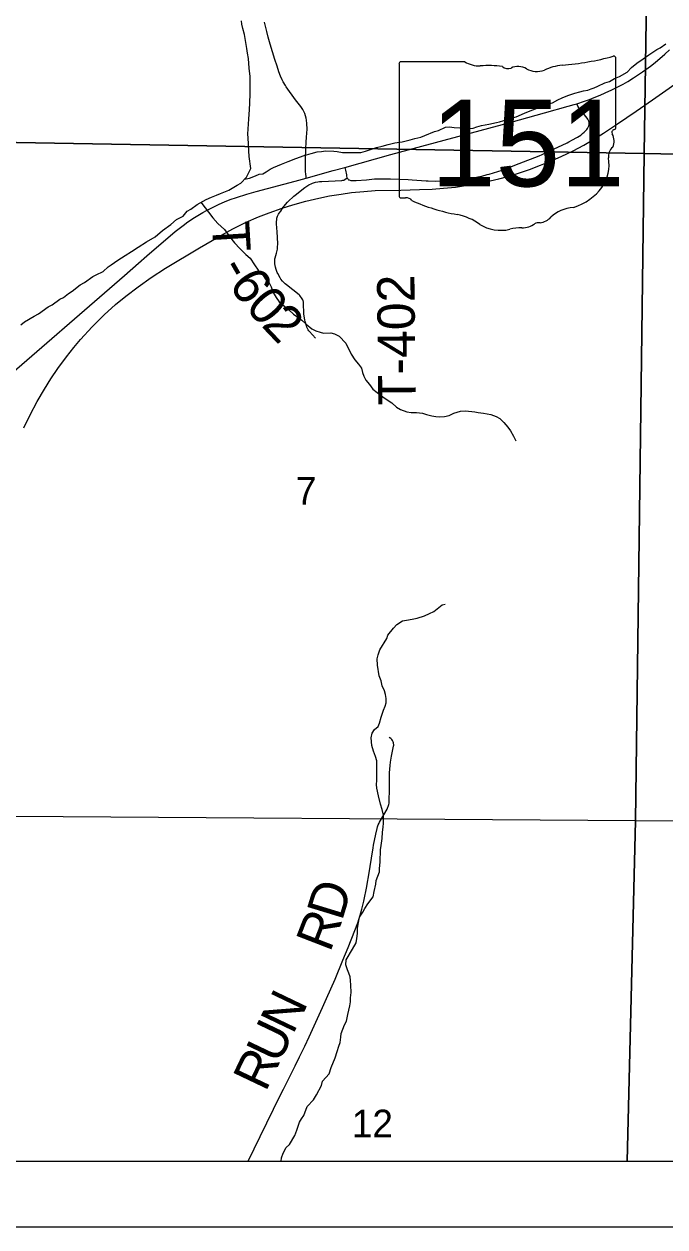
# Model space of a CAD drawing. Extents: x -1.2 to 34, y -8.5 to 22.
# Drawn here: x 3.48 to 4.454, y 14 to 15.827 of the extents above; entities that cross this region are included whole.
import ezdxf

# ---------------------------------------------------------------- set-up
doc = ezdxf.new("R2010")
doc.units = 0
for name, color, linetype in [('GM_X_Minor_River', 7, 'Continuous'), ('GM_X_Rail_Line', 7, 'Continuous'), ('GM_X_Section', 7, 'Continuous'), ('GM_X_Section_Text', 7, 'Continuous'), ('GM_X_State_Location', 7, 'Continuous'), ('GM_X_State_Route', 7, 'Continuous'), ('GM_X_State_Shield', 7, 'Continuous'), ('GM_X_Township_Road', 7, 'Continuous'), ('GM_X_Township_Road_Text', 7, 'Continuous'), ('GM_X_Unincorporated_Text', 7, 'Continuous'), ('SH_Cut_Line', 7, 'Continuous'), ('SH_Data', 7, 'Continuous')]:
    doc.layers.add(name, color=color, linetype=linetype)

msp = doc.modelspace()

# ---------------------------------------------------------------- linework, layer by layer
at = {"layer": 'GM_X_Minor_River'}
for points in [[(3.4755, 15.3701), (3.4808, 15.3747), (3.4954, 15.3833), (3.5022, 15.3869), (3.5168, 15.3977), (3.5232, 15.4009), (3.5344, 15.4094), (3.54, 15.4118), (3.5479, 15.418), (3.5535, 15.4215), (3.5655, 15.4312), (3.5719, 15.4347), (3.5846, 15.4437), (3.5899, 15.4464), (3.6004, 15.4512), (3.6079, 15.4585), (3.6128, 15.4616), (3.6225, 15.4686), (3.6341, 15.4757), (3.6435, 15.4815), (3.6536, 15.4885), (3.6664, 15.4963), (3.6795, 15.5038), (3.6908, 15.5135), (3.7031, 15.5228), (3.7117, 15.5305), (3.7219, 15.5353), (3.7282, 15.543), (3.7338, 15.5461), (3.7432, 15.5531), (3.7567, 15.5609), (3.765, 15.5641), (3.7725, 15.5672), (3.7785, 15.57), (3.7913, 15.5748), (3.7988, 15.5794), (3.8041, 15.5826), (3.8097, 15.5853), (3.8179, 15.5946), (3.8246, 15.608), (3.8224, 15.6262), (3.8219, 15.6346), (3.8205, 15.6544), (3.8204, 15.6597), (3.8206, 15.6681), (3.8213, 15.6749), (3.8216, 15.6833), (3.8225, 15.697), (3.8231, 15.7077), (3.8237, 15.7214), (3.8238, 15.7355), (3.8237, 15.7473), (3.8223, 15.7602), (3.821, 15.7747), (3.8197, 15.783), (3.8185, 15.7899), (3.8152, 15.8111), (3.8127, 15.8206), (3.8111, 15.827), (3.8103, 15.832)], [(3.8151, 15.5914), (3.8229, 15.5931), (3.8319, 15.5967), (3.8372, 15.5991), (3.8432, 15.5999), (3.8481, 15.6027), (3.8541, 15.6066), (3.8594, 15.6093), (3.8714, 15.6141), (3.8816, 15.6184), (3.8932, 15.6231), (3.9057, 15.6275), (3.9166, 15.6307), (3.9253, 15.6332), (3.9321, 15.6336), (3.9381, 15.6345), (3.9506, 15.6339), (3.9556, 15.6336), (3.9639, 15.6322), (3.9757, 15.632), (3.9916, 15.6323), (3.9987, 15.6339), (4.0051, 15.6359), (4.0157, 15.6399), (4.024, 15.6415), (4.0334, 15.6443), (4.0436, 15.6468), (4.0546, 15.6481), (4.0666, 15.6513), (4.0738, 15.6533), (4.0828, 15.6554), (4.0889, 15.6581), (4.1035, 15.6641), (4.1096, 15.6657), (4.1205, 15.6704), (4.1265, 15.6709), (4.1334, 15.6702), (4.1421, 15.6696), (4.1493, 15.669), (4.1569, 15.6687), (4.1622, 15.6691), (4.1678, 15.6711), (4.175, 15.6732), (4.1863, 15.6752), (4.1976, 15.6777), (4.2025, 15.6785), (4.2089, 15.6805), (4.2221, 15.6849), (4.2278, 15.6861), (4.2402, 15.6917), (4.2466, 15.6944), (4.2594, 15.6996), (4.2714, 15.7047), (4.2831, 15.7075), (4.291, 15.7122), (4.2974, 15.715), (4.3061, 15.7189), (4.317, 15.7222), (4.3242, 15.7242), (4.3302, 15.7258), (4.3366, 15.727), (4.3415, 15.729), (4.3464, 15.7302), (4.3517, 15.733), (4.3626, 15.7377), (4.3694, 15.7401), (4.3773, 15.7444), (4.3844, 15.7476), (4.3964, 15.7542), (4.4028, 15.7612), (4.411, 15.7678), (4.4204, 15.7744), (4.4294, 15.7806), (4.4414, 15.7884), (4.4462, 15.7911), (4.4552, 15.797)], [(3.7489, 15.5564), (3.767, 15.5329), (3.7747, 15.5243), (3.7846, 15.5149), (3.7924, 15.5044), (3.7997, 15.495), (3.8082, 15.486), (3.817, 15.477), (3.8235, 15.4717), (3.8301, 15.4616), (3.8359, 15.4533), (3.8424, 15.4465), (3.8471, 15.4397), (3.8525, 15.4341), (3.8556, 15.4281), (3.8587, 15.4194), (3.8634, 15.4118), (3.8676, 15.4054), (3.8765, 15.3979), (3.8822, 15.3931), (3.8895, 15.3867), (3.896, 15.3819), (3.9021, 15.3774), (3.909, 15.3714), (3.9175, 15.3643), (3.9236, 15.3614), (3.93, 15.3592), (3.935, 15.3577), (3.946, 15.3579), (3.952, 15.3565), (3.9589, 15.3532), (3.9689, 15.3426), (3.9771, 15.3256), (3.9829, 15.317), (3.9883, 15.3106), (3.9929, 15.3046), (3.9945, 15.2981), (3.9965, 15.2921), (3.9996, 15.286), (4.0047, 15.2796), (4.0101, 15.2725), (4.0166, 15.2673), (4.0273, 15.2594), (4.0388, 15.252), (4.046, 15.2453), (4.0518, 15.2415), (4.0617, 15.2383), (4.0681, 15.2372), (4.0761, 15.237), (4.0856, 15.2363), (4.0916, 15.2342), (4.0996, 15.232), (4.1057, 15.2309), (4.1106, 15.2303), (4.119, 15.2308), (4.1257, 15.2328), (4.1329, 15.2359), (4.1431, 15.2391), (4.1506, 15.2396), (4.1647, 15.2383), (4.17, 15.2373), (4.1783, 15.2359), (4.189, 15.2341), (4.1973, 15.2312), (4.2031, 15.2279), (4.2088, 15.2219), (4.215, 15.2147), (4.2192, 15.2095), (4.2235, 15.2012), (4.2273, 15.1942)], [(3.9699, 14.3127), (3.9721, 14.3226), (3.9749, 14.336), (3.976, 14.3417), (3.9762, 14.3482), (3.9769, 14.3562), (3.9767, 14.3672), (3.9762, 14.3741), (3.9754, 14.3798), (3.9734, 14.3855), (3.9715, 14.3904), (3.9691, 14.398), (3.9697, 14.4056), (3.9793, 14.4221), (3.9845, 14.4313), (3.9859, 14.4382), (3.9866, 14.4458), (3.9868, 14.4534), (3.9879, 14.4599), (3.99, 14.4706), (3.9948, 14.4783), (3.9981, 14.4837), (4.0026, 14.4906), (4.0104, 14.5014), (4.0121, 14.5094), (4.0146, 14.5205), (4.0153, 14.5262), (4.02, 14.5392), (4.0199, 14.5441), (4.0209, 14.5548), (4.0212, 14.5609), (4.0215, 14.5662), (4.0218, 14.5727), (4.0228, 14.5792), (4.0242, 14.5899), (4.0248, 14.5998), (4.0258, 14.607), (4.0261, 14.6131), (4.026, 14.6253), (4.0243, 14.634), (4.0219, 14.642), (4.0187, 14.6549), (4.0159, 14.6663), (4.0154, 14.672), (4.0161, 14.6781), (4.0163, 14.6887), (4.0162, 14.6971), (4.016, 14.7081), (4.014, 14.7146), (4.0109, 14.7229), (4.0085, 14.7312), (4.0076, 14.743), (4.009, 14.7499), (4.0127, 14.7556), (4.0179, 14.7599), (4.0201, 14.7653), (4.0226, 14.7741), (4.0263, 14.7852), (4.0288, 14.7909), (4.0303, 14.7963), (4.0302, 14.8027), (4.0293, 14.8088), (4.0277, 14.8145), (4.0242, 14.8221), (4.0226, 14.8296), (4.0198, 14.8372), (4.0173, 14.8532), (4.0168, 14.863), (4.0182, 14.8692), (4.0208, 14.8764), (4.0315, 14.8937), (4.0329, 14.8987), (4.0415, 14.9095), (4.0463, 14.9153), (4.0553, 14.9207), (4.0644, 14.9224), (4.0723, 14.9237), (4.0776, 14.9249), (4.0885, 14.9285), (4.0961, 14.932), (4.1028, 14.9348), (4.1152, 14.9452), (4.1201, 14.9461)], [(3.871, 14.1), (3.8715, 14.1049), (3.8737, 14.1118), (3.8785, 14.1206), (3.8833, 14.1253), (3.8915, 14.1391), (3.8947, 14.1471), (3.8987, 14.159), (3.9017, 14.164), (3.905, 14.1694), (3.9101, 14.1828), (3.9198, 14.1932), (3.9243, 14.2005), (3.932, 14.2147), (3.9334, 14.2216), (3.9435, 14.2324), (3.9467, 14.2423), (3.9526, 14.2569), (3.9559, 14.2664), (3.9584, 14.2745), (3.9606, 14.2802), (3.9612, 14.2882), (3.9619, 14.2939), (3.967, 14.307), (3.9699, 14.3127)]]:
    msp.add_lwpolyline(points, dxfattribs=at)
at = {"layer": 'GM_X_Rail_Line'}
msp.add_lwpolyline([(3.4799, 15.2138), (3.4895, 15.2336), (3.5002, 15.254), (3.5111, 15.2726), (3.5209, 15.2883), (3.5317, 15.3039), (3.5446, 15.3216), (3.5559, 15.336), (3.5662, 15.348), (3.5835, 15.3671), (3.6021, 15.3855), (3.6194, 15.4012), (3.6349, 15.414), (3.6535, 15.4282), (3.6731, 15.442), (3.6951, 15.4564), (3.7467, 15.4873), (3.7754, 15.5039), (3.7975, 15.516), (3.8176, 15.526), (3.8366, 15.5341), (3.8527, 15.5405), (3.8722, 15.5477), (3.8883, 15.5527), (3.9083, 15.5583), (3.928, 15.5629), (3.9444, 15.5663), (3.962, 15.569), (3.9778, 15.5713), (3.9961, 15.573), (4.0135, 15.5742), (4.0524, 15.5751), (4.0811, 15.5758), (4.1003, 15.5765), (4.1172, 15.5777), (4.1354, 15.5796), (4.1508, 15.5817), (4.1623, 15.5836), (4.1758, 15.5862), (4.1882, 15.5889), (4.2012, 15.592), (4.2148, 15.5956), (4.2299, 15.6001), (4.2482, 15.6063), (4.2646, 15.6126), (4.2798, 15.6188), (4.2963, 15.6261), (4.3145, 15.6348), (4.3307, 15.6433), (4.3455, 15.6522), (4.3603, 15.6614), (4.3818, 15.6754), (4.41, 15.6949), (4.435, 15.7123), (4.4888, 15.7499)], dxfattribs=at)
at = {"layer": 'GM_X_Section'}
for points in [[(3.4269, 16.668), (4.4375, 16.6421), (4.4223, 15.6306), (3.4107, 15.6483)], [(3.4107, 15.6483), (4.4223, 15.6306), (4.409, 14.6166), (3.3946, 14.624)], [(4.4223, 15.6306), (5.4262, 15.6104), (5.4125, 14.6774), (5.4116, 14.6095), (4.409, 14.6166)], [(3.388, 14.1), (4.3964, 14.1), (4.409, 14.6166), (3.3946, 14.624)], [(4.3964, 14.1), (5.4061, 14.1), (5.4116, 14.6095), (4.409, 14.6166)]]:
    msp.add_lwpolyline(points, close=True, dxfattribs=at)
msp.add_lwpolyline([(5.4357, 16.2314), (5.428, 15.6979), (5.4262, 15.6104), (4.4223, 15.6306), (4.4375, 16.6421), (5.3129, 16.6148)], dxfattribs=at)
at = {"layer": 'GM_X_State_Route'}
msp.add_lwpolyline([(3.4385, 15.2772), (3.6326, 15.4453), (3.6543, 15.4641), (3.6668, 15.4751), (3.7099, 15.512), (3.722, 15.5213), (3.7291, 15.5265), (3.7393, 15.5332), (3.7419, 15.5349), (3.752, 15.541), (3.7574, 15.5439), (3.7696, 15.5502), (3.7767, 15.5538), (3.7849, 15.5572), (3.7935, 15.5606), (3.8028, 15.5638), (3.8187, 15.5687), (3.833, 15.573), (3.8922, 15.5887), (3.9089, 15.5932), (3.9496, 15.6045), (3.9676, 15.6093), (4.0376, 15.6288), (4.2202, 15.6784), (4.2708, 15.6925), (4.3066, 15.7025), (4.3159, 15.7051), (4.32, 15.7062), (4.3316, 15.7102), (4.339, 15.7128), (4.3463, 15.7156), (4.3554, 15.7192), (4.3631, 15.7226), (4.3731, 15.7271), (4.3823, 15.7317), (4.3904, 15.7361), (4.3971, 15.74), (4.4061, 15.7457), (4.4137, 15.7505), (4.4198, 15.7548), (4.4318, 15.7634), (4.439, 15.7689), (4.4535, 15.7816), (4.4606, 15.7878)], dxfattribs=at)
at = {"layer": 'GM_X_State_Shield'}
for p, q in [((4.1495, 15.77), (4.053, 15.77)), ((4.3793, 15.6703), (4.3793, 15.775)), ((4.0498, 15.7666), (4.0498, 15.5665)), ((4.3793, 15.6703), (4.3793, 15.6703))]:
    msp.add_line(p, q, dxfattribs=at)
for centre, major_axis, start_param, end_param in [((4.0535, 15.767), (0.00382, 0), 1.712693, 3.28349), ((4.1725, 15.7932), (0.037, 0), 4.042523, 4.731795), ((4.2619, 16.0428), (0.3495, 0), 4.814394, 5.042369), ((4.3757, 15.7754), (0.00367, 0), 6.141152, 7.989035), ((4.1848, 15.6577), (0.133, 0), 1.404758, 1.657858), ((4.215, 15.768), (0.0107, 0), 3.836095, 5.185415), ((4.2307, 15.7449), (0.0222, 0), 0.950623, 2.079405), ((4.2593, 15.7766), (0.0267, 0), 4.081561, 5.145723), ((4.3065, 15.7089), (0.0703, 0), 1.699011, 2.107814), ((4.3785, 15.6626), (0.00568, 0), 1.883978, 3.671073), ((4.3424, 15.6494), (0.0341, 0), 5.934695, 6.695948), ((4.3754, 15.6699), (0.00393, 0), 5.05454, 6.418171), ((4.2815, 15.6132), (0.0874, 0), 5.101752, 6.440018), ((4.3925, 15.6265), (0.0248, 0), 2.387724, 3.262537), ((4.0536, 15.566), (0.00385, 0), 3.00124, 4.508301), ((4.0542, 15.5865), (0.0294, 0), 4.665946, 4.897461), ((4.0602, 15.5549), (0.0106, 0), 0.519207, 1.627899), ((4.194, 15.7347), (0.2524, 0), 4.195997, 4.488961), ((4.1188, 15.4765), (0.079, 0), 0.823519, 1.323587), ((4.2577, 15.5471), (0.0282, 0), 4.937069, 5.64225), ((4.3184, 15.5103), (0.0479, 0), 1.647645, 2.488434), ((4.2042, 15.5539), (0.0501, 0), 4.026481, 4.996735), ((4.2331, 15.4847), (0.0412, 0), 1.495662, 1.94098), ((4.2368, 15.5389), (0.0267, 0), 4.691044, 5.507374), ((4.2609, 15.5195), (0.00752, 0), 1.147584, 2.315152)]:
    msp.add_ellipse(centre, major_axis=major_axis, ratio=0.8, start_param=start_param, end_param=end_param, dxfattribs=at)
at = {"layer": 'GM_X_Township_Road'}
for points in [[(3.9089, 15.5932), (3.9086, 15.5951), (3.9082, 15.5995), (3.9078, 15.6028), (3.9077, 15.6052), (3.9076, 15.609), (3.9075, 15.6128), (3.9077, 15.6175), (3.9078, 15.622), (3.9084, 15.6375), (3.909, 15.6478), (3.9095, 15.6553), (3.9098, 15.6613), (3.9101, 15.6673), (3.9098, 15.6763), (3.9095, 15.681), (3.909, 15.6842), (3.908, 15.688), (3.9068, 15.6911), (3.9053, 15.6942), (3.9035, 15.6973), (3.9005, 15.702), (3.8928, 15.7122), (3.8785, 15.7317), (3.8773, 15.7336), (3.8739, 15.7394), (3.8725, 15.7423), (3.87, 15.7481), (3.8675, 15.7545), (3.8645, 15.7634), (3.8613, 15.7732), (3.8542, 15.7966), (3.8511, 15.8074), (3.849, 15.8157), (3.8457, 15.8299)], [(3.9676, 15.6093), (3.968, 15.6075), (3.9685, 15.6052), (3.9699, 15.5983), (3.9702, 15.5959), (3.9707, 15.5941), (3.971, 15.5934), (3.9715, 15.5925), (3.9723, 15.5915), (3.9732, 15.5908), (3.9741, 15.5904), (3.9764, 15.5897), (3.9774, 15.5895), (3.9827, 15.5894), (3.9849, 15.5895), (4.0002, 15.5908), (4.0124, 15.5919), (4.0179, 15.5921), (4.022, 15.5922), (4.0369, 15.5923), (4.0638, 15.5912), (4.07, 15.5907), (4.0909, 15.589), (4.0941, 15.5888), (4.1049, 15.5886), (4.1177, 15.5888), (4.1244, 15.5894), (4.1297, 15.5898), (4.137, 15.5905), (4.1435, 15.591), (4.1484, 15.5916), (4.1549, 15.5925), (4.16, 15.5933), (4.1651, 15.594), (4.1696, 15.5949), (4.1754, 15.5962), (4.1836, 15.5984), (4.1867, 15.5992), (4.2063, 15.6053), (4.2091, 15.6062), (4.2323, 15.6153), (4.2624, 15.627), (4.2671, 15.6289), (4.2714, 15.6309), (4.3051, 15.6468), (4.3079, 15.6481), (4.3134, 15.6512), (4.3197, 15.6547), (4.3208, 15.6553), (4.3257, 15.6584), (4.3286, 15.6607), (4.3311, 15.663), (4.3336, 15.6656), (4.3349, 15.6669), (4.3361, 15.6685), (4.3373, 15.6704), (4.3383, 15.6727), (4.3386, 15.6744), (4.3388, 15.676), (4.3386, 15.678), (4.3383, 15.6791), (4.3381, 15.6799), (4.3378, 15.6809), (4.3366, 15.6829), (4.3355, 15.6843), (4.3313, 15.6891), (4.3281, 15.6927), (4.3239, 15.698), (4.323, 15.6994), (4.3223, 15.7007), (4.3215, 15.7024), (4.32, 15.7062)], [(3.9229, 15.3501), (3.9136, 15.3602), (3.9128, 15.361), (3.9119, 15.3627), (3.91, 15.3669), (3.9093, 15.3686), (3.9074, 15.3754), (3.9069, 15.3773), (3.9054, 15.3872), (3.9051, 15.389), (3.9048, 15.4011), (3.9046, 15.4048), (3.9041, 15.4072), (3.9037, 15.4085), (3.9028, 15.4099), (3.8989, 15.4149), (3.898, 15.4158), (3.879, 15.4308), (3.8769, 15.4325), (3.8736, 15.4357), (3.8728, 15.4365), (3.8703, 15.4398), (3.8691, 15.4417), (3.8656, 15.4481), (3.8648, 15.4498), (3.8633, 15.4543), (3.8623, 15.4581), (3.8614, 15.4632), (3.8611, 15.4651), (3.8614, 15.4707), (3.8616, 15.4719), (3.8635, 15.4794), (3.865, 15.4853), (3.8653, 15.4876), (3.8657, 15.4938), (3.8646, 15.5117), (3.8639, 15.5238), (3.8639, 15.5263), (3.8641, 15.5308), (3.8643, 15.5322), (3.8652, 15.5354), (3.8655, 15.5363), (3.8667, 15.5382), (3.8695, 15.5421), (3.8704, 15.5432), (3.8739, 15.5488), (3.8746, 15.5498), (3.8804, 15.5564), (3.8814, 15.5576), (3.8901, 15.5656), (3.8921, 15.5672), (3.9068, 15.5787), (3.9112, 15.5819), (3.9127, 15.5828), (3.9174, 15.5852), (3.9182, 15.5856), (3.9229, 15.587), (3.9264, 15.5877), (3.9292, 15.588), (3.9325, 15.5881), (3.9627, 15.5896), (3.9646, 15.5898), (3.966, 15.5902), (3.9677, 15.591), (3.971, 15.5934)], [(3.8206, 14.1), (3.8387, 14.1372), (3.8692, 14.1997), (3.8741, 14.2093), (3.8919, 14.2445), (3.8986, 14.2582), (3.9066, 14.2748), (3.9132, 14.2889), (3.9337, 14.3333), (3.9397, 14.3468), (3.9526, 14.3765), (3.9646, 14.4051), (3.9725, 14.4245), (3.9827, 14.4503), (3.9871, 14.4619), (3.9894, 14.4685), (3.991, 14.4736), (3.9934, 14.4828), (3.9961, 14.4946), (4.0009, 14.5171), (4.0021, 14.5238), (4.0035, 14.5316), (4.0104, 14.576), (4.0111, 14.5798), (4.0146, 14.5968), (4.0165, 14.605), (4.0172, 14.6077), (4.0182, 14.6108), (4.0194, 14.6135), (4.02, 14.6147), (4.0316, 14.6348), (4.0323, 14.6362), (4.0339, 14.6401), (4.0344, 14.6419), (4.0346, 14.6437), (4.0349, 14.6496), (4.0351, 14.6621), (4.0352, 14.6839), (4.0355, 14.6899), (4.0363, 14.7009), (4.0369, 14.7061), (4.0384, 14.7151), (4.0393, 14.7199), (4.0415, 14.7301), (4.0417, 14.7319), (4.0414, 14.7354), (4.0409, 14.737), (4.04, 14.7387), (4.0387, 14.7403), (4.0371, 14.742), (4.035, 14.7435)]]:
    msp.add_lwpolyline(points, dxfattribs=at)
at = {"layer": 'GM_X_Unincorporated_Text'}
msp.add_line((2.3586, 14.1), (8.2551, 14.1), dxfattribs=at)
at = {"layer": 'SH_Cut_Line'}
msp.add_lwpolyline([(4.6867, 17.6371), (4.4093, 17.6489), (4.1759, 17.654), (3.3984, 17.6707), (2.8968, 17.6806), (2.4258, 17.6899), (2.4189, 17.3824), (2.402, 16.1209), (2.3867, 15.3183), (2.3672, 14.6322), (2.3643, 14.4203), (2.3586, 14.1), (8.9, 14.1)], dxfattribs=at)
at = {"layer": 'SH_Data'}
for p, q in [((2.1, 14.1), (8.9, 14.1)), ((2.1, 14.1), (8.9, 14.1)), ((2, 14), (9, 14)), ((2, 14), (9, 14))]:
    msp.add_line(p, q, dxfattribs=at)

# ---------------------------------------------------------------- texts
at = {"layer": 'GM_X_Section_Text'}
for s, height, p in [('7', 0.0419, (3.8932, 15.0972)), ('12', 0.04186, (3.9782, 14.1362))]:
    msp.add_text(s, height=height, rotation=0, dxfattribs=at).set_placement(p)
at = {"layer": 'GM_X_State_Location'}
for s, p in [('s', (4.2109, 15.6532)), ('r', (4.2108, 15.6532))]:
    msp.add_text(s, height=0.000189, dxfattribs=at).set_placement(p)
msp.add_text('151', height=0.000189, rotation=0, dxfattribs=at).set_placement((4.144, 15.6394))
at = {"layer": 'GM_X_State_Shield'}
msp.add_text('151', height=0.13184, dxfattribs=at).set_placement((4.0983, 15.5806))
at = {"layer": 'GM_X_Township_Road_Text'}
for s, height, rotation, p in [('T', 0.0568, 273.4026, (3.7654, 15.5258)), ('-', 0.0568, 299.7705, (3.776, 15.4562)), ('6', 0.0568, 304.4085, (3.7902, 15.4317)), ('T-402', 0.05682, 90.5614, (4.0751, 15.2484)), ('0', 0.0568, 311.8339, (3.815, 15.3966)), ('2', 0.0568, 313.5001, (3.8395, 15.3691)), ('D', 0.0568, 73.0228, (3.9631, 14.4635)), ('R', 0.0568, 68.8871, (3.9449, 14.4158)), ('N', 0.0568, 64.3734, (3.8887, 14.291)), ('U', 0.0568, 64.5363, (3.8672, 14.2459)), ('R', 0.0568, 64.5382, (3.8471, 14.2038))]:
    msp.add_text(s, height=height, rotation=rotation, dxfattribs=at).set_placement(p)

doc.saveas('drawing.dxf')
